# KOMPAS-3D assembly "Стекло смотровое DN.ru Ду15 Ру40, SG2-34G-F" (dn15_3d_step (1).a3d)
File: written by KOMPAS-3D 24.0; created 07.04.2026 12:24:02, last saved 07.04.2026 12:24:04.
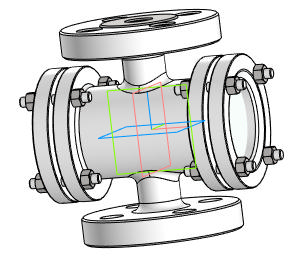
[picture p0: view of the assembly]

Document properties: Автор: Main; Полное имя файла: D:\DN.ru Аутсерс\Стекло смотровое DN.ru\Исходники\Стекло смотровое DN.ru SG2-34G-F тип В ГОСТ 21836-2021 Ду15 Ру40, углеродистая сталь, фланцевое\dn15_3d_step (1).a3d

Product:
- Component [detail]: Деталь  | qty 1  | pos. 1  | Масса: 2.979461; Автор: Main; additional columns: Типовые; source file: ДетальДеталь.m3d
- Component [detail]: Стекло  | qty 2  | pos. 2  | Масса: 0.08342; Автор: Main; source file: СтеклоСтекло.m3d
- Component [detail]: ANSI B18.2.4.2M - M6x1 - 10  | designation ANSI B18.2.4.2M - M6x1  | qty 16  | pos. 3  | Масса: 0.003008; Комментарий: Типы метрических   шестигранных гаек   2; Автор: Main; additional columns: Сталь, мягкая; source file: ANSI B18.2.4.2M - M6x1ANSI B18.2.4.2M - M6x1 - 10.m3d
- Part/product: Стекло смотровое DN.ru Ду15 Ру40  | designation SG2-34G-F
    Масса: 4
    Раздел спецификации: Прочие изделия
    Примечание: D500-00079

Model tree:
1. Массив по концентрической сетке:1  (labels: Грань.Твердое тело1; Ребро.Solid1; Ребро.Твердое тело1; Грань.Solid1)  (4 pattern instances)
     Шаг 2 = 360

Expressions: SG2-34G-F
Referenced files in D:\DN.ru Аутсерс\Стекло смотровое DN.ru\Исходники\Стекло смотровое DN.ru SG2-34G-F тип В ГОСТ 21836-2021 Ду15 Ру40, углеродистая сталь, фланцевое\: ДетальДеталь.m3d, СтеклоСтекло.m3d, ANSI B18.2.4.2M - M6x1ANSI B18.2.4.2M - M6x1 - 10.m3d
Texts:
  Стекло Стекло (1)
  Стекло Стекло (2)
  ANSI B18.2.4.2M - M6x1 ANSI B18.2.4.2M - M6x1 - 10 (1)
  ANSI B18.2.4.2M - M6x1 ANSI B18.2.4.2M - M6x1 - 10 (2)
  ANSI B18.2.4.2M - M6x1 ANSI B18.2.4.2M - M6x1 - 10 (3)
  ANSI B18.2.4.2M - M6x1 ANSI B18.2.4.2M - M6x1 - 10 (4)
  ANSI B18.2.4.2M - M6x1 ANSI B18.2.4.2M - M6x1 - 10 (5)
  ANSI B18.2.4.2M - M6x1 ANSI B18.2.4.2M - M6x1 - 10 (6)
  ANSI B18.2.4.2M - M6x1 ANSI B18.2.4.2M - M6x1 - 10 (7)
  ANSI B18.2.4.2M - M6x1 ANSI B18.2.4.2M - M6x1 - 10 (8)
  ANSI B18.2.4.2M - M6x1 ANSI B18.2.4.2M - M6x1 - 10 (9)
  ANSI B18.2.4.2M - M6x1 ANSI B18.2.4.2M - M6x1 - 10 (10)
  ANSI B18.2.4.2M - M6x1 ANSI B18.2.4.2M - M6x1 - 10 (11)
  ANSI B18.2.4.2M - M6x1 ANSI B18.2.4.2M - M6x1 - 10 (12)
  ANSI B18.2.4.2M - M6x1 ANSI B18.2.4.2M - M6x1 - 10 (13)
  ANSI B18.2.4.2M - M6x1 ANSI B18.2.4.2M - M6x1 - 10 (14)
  ANSI B18.2.4.2M - M6x1 ANSI B18.2.4.2M - M6x1 - 10 (15)
  ANSI B18.2.4.2M - M6x1 ANSI B18.2.4.2M - M6x1 - 10 (16)
  Ось Z.Начало координат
